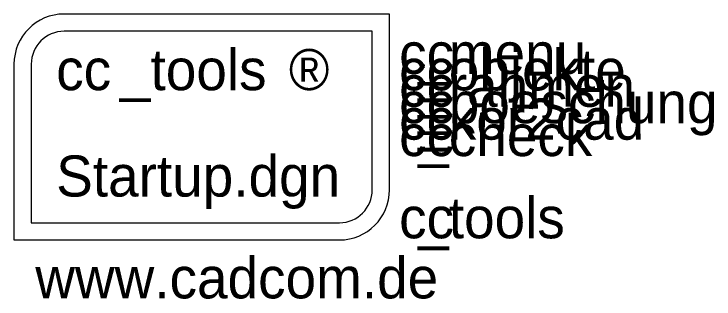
# Model space of a CAD drawing. Extents: x -0.11 to 4.16, y -0.46 to 1.27.
import ezdxf

# ---------------------------------------------------------------- set-up
doc = ezdxf.new("R2010")
doc.units = 0
doc.layers.add('Default', color=7, linetype='Continuous')

msp = doc.modelspace()

# ---------------------------------------------------------------- linework, layer by layer
at = {"layer": 'Default'}
for p, q in [((0, 0.9645), (0, 0)), ((0, 0), (1.8755, 0))]:
    msp.add_line(p, q, dxfattribs=at)
for points in [[(2.1805, 0.2), (2.1805, 1.2696), (0.2, 1.2696)], [(2.0755, 0.2), (2.0755, 1.1645), (0.2, 1.1645)], [(-0.1051, 0.9645), (-0.1051, -0.1051), (1.8755, -0.1051)]]:
    msp.add_lwpolyline(points, dxfattribs=at)
for centre, radius, start, end in [((0.2, 0.9645), 0.3051, 90, 180), ((0.2, 0.9645), 0.2, 90, 180), ((1.8755, 0.2), 0.2, 270, 360), ((1.8755, 0.2), 0.3051, 270, 0)]:
    msp.add_arc(centre, radius, start, end, dxfattribs=at)

# ---------------------------------------------------------------- texts
for s, p in [('_tools', (0.54, 0.8061)), ('cc', (2.239, 0.9051)), ('_menu', (2.3555, 0.9051)), ('_objekte', (2.3555, 0.8051)), ('®', (1.5684, 0.8061)), ('cc', (0.1517, 0.8061)), ('cc', (2.239, 0.8051)), ('_rahmen', (2.3555, 0.7051)), ('cc', (2.239, 0.7051)), ('_boeschung', (2.3555, 0.6051)), ('cc', (2.239, 0.6051)), ('_kor2cad', (2.3555, 0.5051)), ('cc', (2.239, 0.5051)), ('_check', (2.3555, 0.4051)), ('cc', (2.239, 0.4051)), ('Startup.dgn', (0.1517, 0.159)), ('_tools', (2.3555, -0.0949)), ('cc', (2.239, -0.0949)), ('www.cadcom.de', (0.0245, -0.4606))]:
    msp.add_text(s, height=0.25, dxfattribs=at).set_placement(p)

doc.saveas('drawing.dxf')
